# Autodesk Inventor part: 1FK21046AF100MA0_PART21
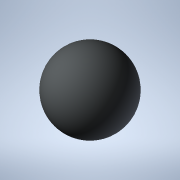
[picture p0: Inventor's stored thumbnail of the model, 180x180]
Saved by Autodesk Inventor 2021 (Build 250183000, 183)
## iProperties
Created: 2025-04
Part Number: 1FK21046AF100MA0_PART21
Material: Generic
Catalog Web Link: www.3dfindit.com
Description: -Servo synchronous motor
Document SubType Name: Modeling
Designer: psAdmin
Mass: 0.137258 g
Surface Area: 1.2868 cm^2
Volume: 0.137258 cm^3
Density: 1 g/cm^3
Appearance: PSOLRGB-212-217-219
Category: PARTsolutions
Title: 1FK21046AF100MA0_PART21
Author: Cadenas PARTsolutions
Comments: Servo synchronous motor
Sending System: PARTsolutions
Preprocessor: ST-DEVELOPER v19.3
PSOL_IDENT_0: {$CADENAS_DATA/23d-libs/siemens_ag/_cat_/4f/2b/1fk21046af100ma0.prj},216 {VTYP=3D},{NB=1FK21046AF100
PSOL_IDENT_1: MA0_PART21},{LINA=1FK21046AF100MA0_PART21},{NN=1FK21046AF100MA0_PART21},{NOPRJ=TRUE},{DATE=19.08.202
PSOL_IDENT_2: 5 14:00:37},{GEOMDATE=30.07.2025 02:01:06},{VERSION=},{LINEID=10},{WBVAR=},{WBNUMERIC=}  {NB=1FK2104
PSOL_IDENT_3: 6AF100MA0_PART21},{LINA=1FK21046AF100MA0_PART21},{KT=DUMMY},{PREVIEW=../../../_pool_/cb/72/p_d211_xx
PSOL_IDENT_4: _00434j.png},{DESCSHORT=SIMOTICS S-1FK2 HD, SINAMICS S210 3AC 400V-480V, 3.2 Nm, 3000 rpm},{DESCLONG=
PSOL_IDENT_5: SIMOTICS S-1FK2 HD servo motor M0=3.2 Nm; PN = 1 kW at nN=3000 rpm (380-480 V); PN = 0.5 kW at nN=15
PSOL_IDENT_6: 00 rpm (200-240 V); with holding brake; degree of protection IP64; cylindrical shaft D19x40mm; absol
PSOL_IDENT_7: ute encoder 22-bit + 12-bit multiturn (encoder AM22DQC); with OCC interface; plug size M17, rotatabl
PSOL_IDENT_8: e; SIMOTICS S-1FK2 servomotorfor a wide range of uses in industrial environments. SIMOTICS S‑1FK2 se
PSOL_IDENT_9: rvomotors are compact synchronous motors with a high dynamic performance that set themselves apart a
PSOL_IDENT_10: s a result of their high power density, degree of protection and overload capability. The motors are
PSOL_IDENT_11: available in two variants: as High Dynamic variant (highest dynamic performance as a result of the
PSOL_IDENT_12: low intrinsic moment of inertia for applications demanding a high dynamic performance with low moved
PSOL_IDENT_13: masses) - and as Compact variant (precise and stable closed-loop control for medium up to large mov
PSOL_IDENT_14: ed masses as a result of a medium intrinsic moment of inertia). SIMOTICSS‑1FK2 servomotors fully exp
PSOL_IDENT_15: loit their strengths in a system with the SINAMICSS210 frequency converter and simple connection usi
PSOL_IDENT_16: ng the one cable connection (OCC). Advantages include the short control and positioning times, fast
PSOL_IDENT_17: and precise correction of disturbing quantities as well as stable control with a high dynamic perfor
PSOL_IDENT_18: mance. The servo motors can be configured to address a wide range of requirements. For example with
PSOL_IDENT_19: and without holding brake, IP64 or IP65 degree of protection, singleturn or multiturn absolute encod
PSOL_IDENT_20: ers - to name just a few. Further, the servomotors are available in different shaft heights extendin
PSOL_IDENT_21: g from 20 to 100. A shaft sealing ring is available to achieve an IP65 degree of protection and for
PSOL_IDENT_22: subsequent mounting at the motor or as spare part. SIMOTICS - the optimum motor for each and every m
PSOL_IDENT_23: otion control application.},{INTNO=195125049673},{SUPPLIERALTNO=1FK2104-6AF10-0MA0},{MANUID=1FK21046
PSOL_IDENT_24: AF100MA0},{MANUNAME=Siemens},{MANUTYPEDESC=Synchronous motor 1FK2-HD 3.2 NM},{AAU732=SIMOTICS},{AAO0
PSOL_IDENT_25: 57=S-1FK2},{AAU734=SIMOTICS S-1FK2 HD servo motor M0=3.2 Nm; PN = 1 kW at nN=3000 rpm (380-480 V); P
PSOL_IDENT_26: N = 0.5 kW at nN=1500 rpm (200-240 V); with holding brake; degree of protection IP64; cylindrical sh
PSOL_IDENT_27: aft D19x40mm; absolute encoder 22-bit + 12-bit multiturn (encoder AM22DQC); with OCC interface; plug
PSOL_IDENT_28: size M17, rotatable;},{AAW338=Synchronous motor 1FK2-HD 3.2 NM},{AAO742=SIMOTICS},{AAO663=404294869
PSOL_IDENT_29: 4534},{NOCUPEROU=1},{PRICEQUANTITY=1},{QUANTITYMIN=1},{QUANTITYINT=1},{CTN=85015220},{COO=DE},{AAO67
PSOL_IDENT_30: 6=1FK2104-6AF10-0MA0},{AAO677=Siemens AG},{ORDERUNIT=C62},{CONTENTUNIT=C62}
NB: 1FK21046AF100MA0_PART21
NT: Servo synchronous motor
NBSYN: $MANUID._PART21
LINA: 1FK21046AF100MA0_PART21
CATALOG: SIEMENS
PREVIEW: ../../../_pool_/cb/72/p_d211_xx_00434j.png
DESCSHORT: SIMOTICS S-1FK2 HD, SINAMICS S210 3AC 400V-480V, 3.2 Nm, 3000 rpm
DESCLONG: SIMOTICS S-1FK2 HD servo motor M0=3.2 Nm; PN = 1 kW at nN=3000 rpm (380-480 V); PN = 0.5 kW at nN=1500 rpm (200-240 V); with holding brake; degree of protection
INTNO: 195125049673
SUPPLIERALTNO: 1FK2104-6AF10-0MA0
MANUID: 1FK21046AF100MA0
MANUNAME: Siemens
MANUTYPEDESC: Synchronous motor 1FK2-HD 3.2 NM
AAU732: SIMOTICS
AAO057: S-1FK2
AAU734: SIMOTICS S-1FK2 HD servo motor M0=3.2 Nm; PN = 1 kW at nN=3000 rpm (380-480 V); PN = 0.5 kW at nN=1500 rpm (200-240 V); with holding brake; degree of protection
AAW338: Synchronous motor 1FK2-HD 3.2 NM
AAO742: SIMOTICS
AAO663: 4042948694534.0
NOCUPEROU: 1
PRICEQUANTITY: 1
QUANTITYMIN: 1
QUANTITYINT: 1
CTN: 85015220
COO: DE
ARTICLENO: 1FK21046AF100MA0_PART21
BOMINFO: 1FK21046AF100MA0_PART21
CREATOR: CADENAS GmbH
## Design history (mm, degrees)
feature "2025_04_17_14_59_39_0177"
body "Solid1"
